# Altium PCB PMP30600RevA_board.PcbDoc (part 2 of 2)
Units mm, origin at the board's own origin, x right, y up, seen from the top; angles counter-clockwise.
Board outline 78.5 x 61.5 mm, 4 copper layers (Top Layer, 2nd Layer, 3rd Layer, Bottom Layer), stack 2.155 mm thick; 62 components, 27 nets, 174 pads, 413 vias.
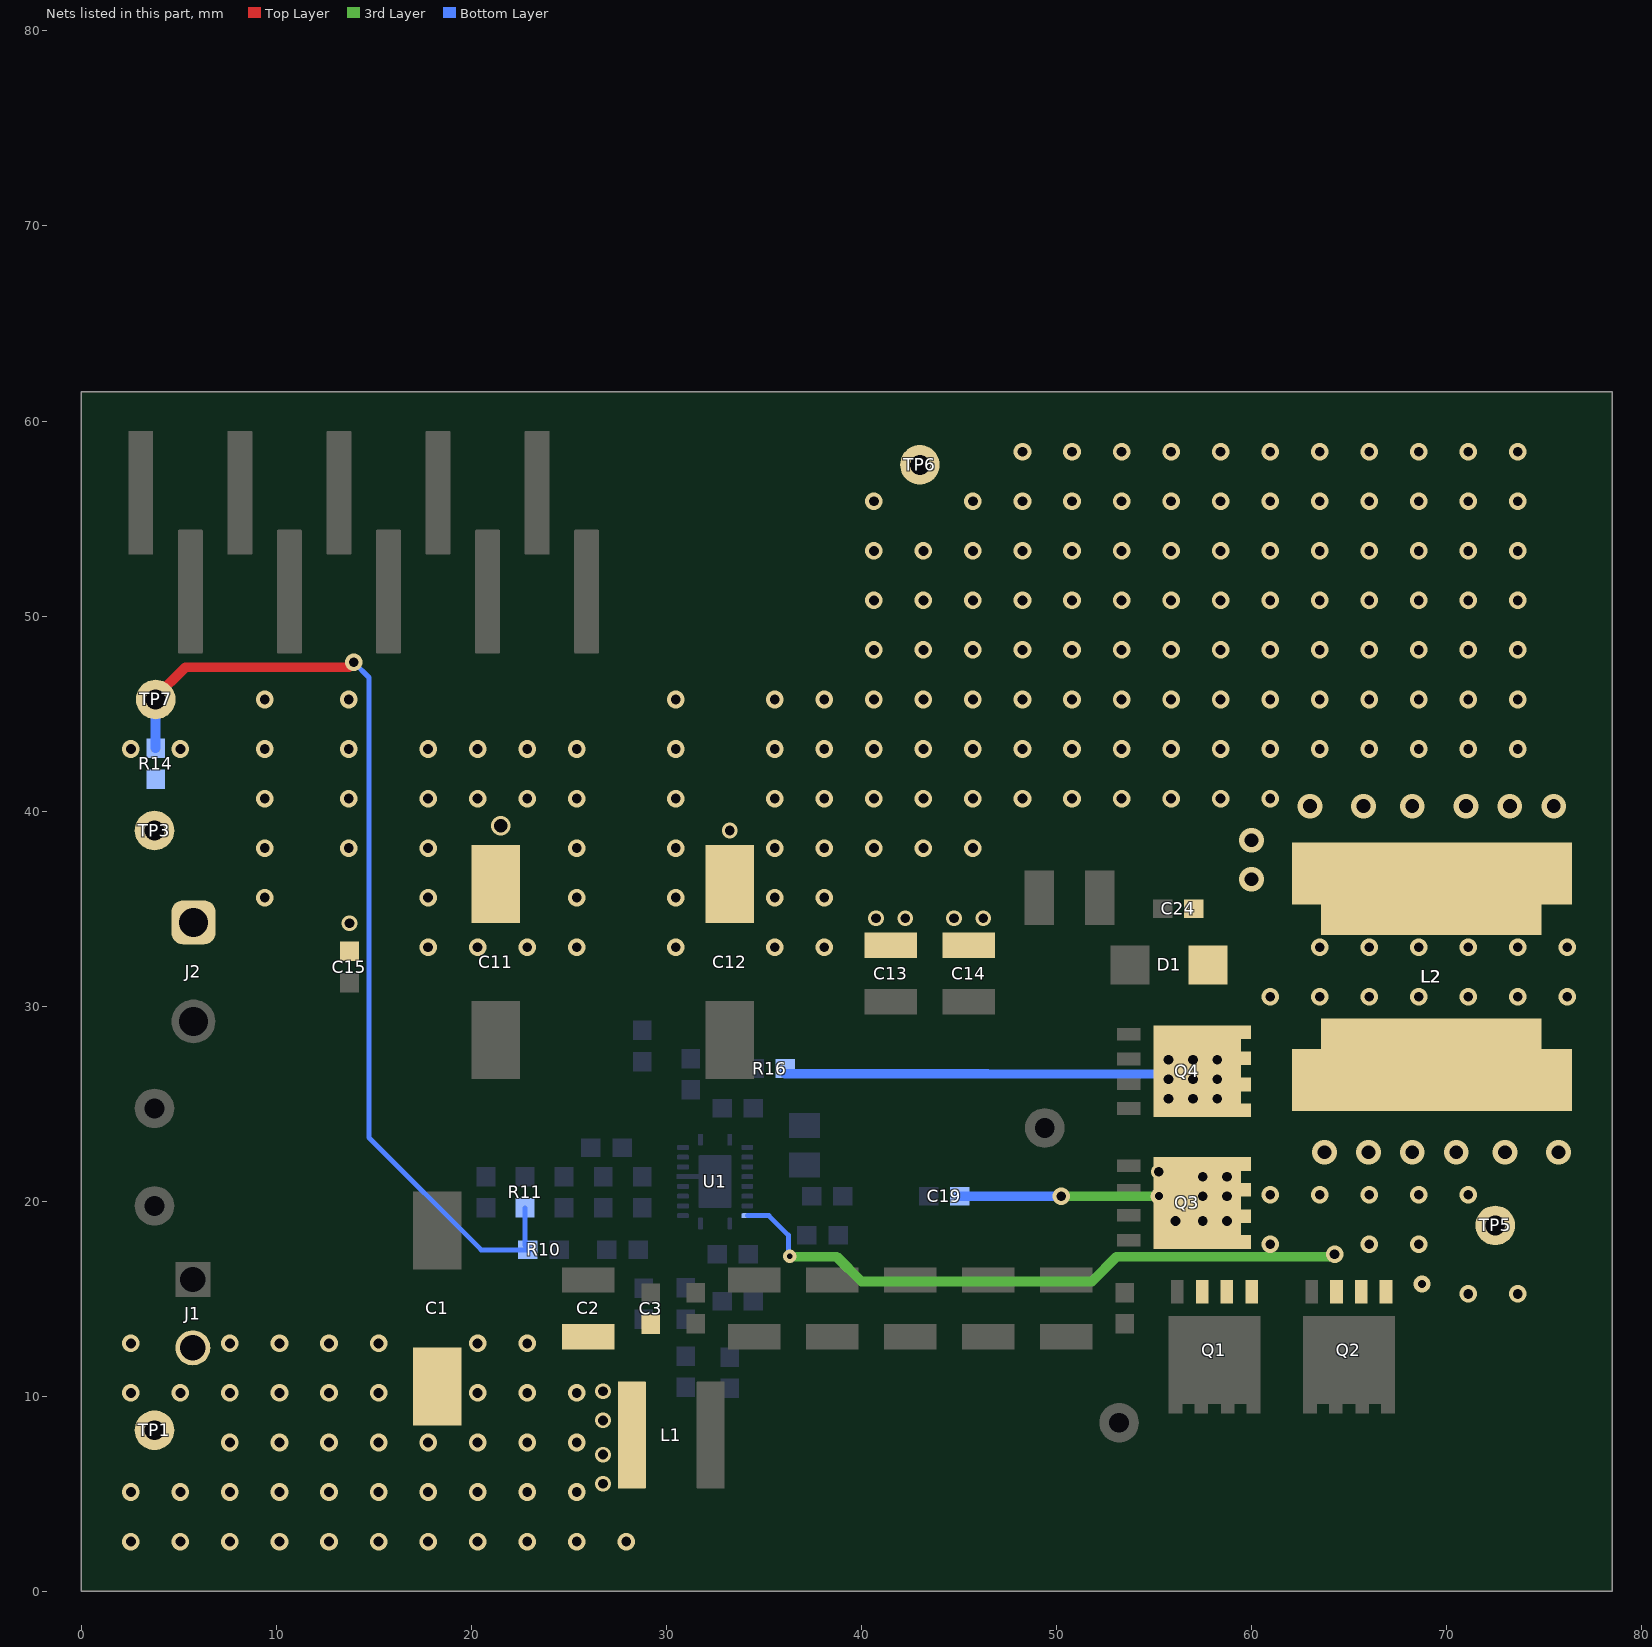
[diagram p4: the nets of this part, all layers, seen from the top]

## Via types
v1: diameter 0.9, hole 0.5, Top Layer to Bottom Layer, 251 vias
v2: diameter 0.9, hole 0.5, Top Layer to Bottom Layer, tented top, 61 vias
v3: diameter 0.8, hole 0.5, Top Layer to Bottom Layer, 57 vias
v4: diameter 0.864, hole 0.406, Top Layer to Bottom Layer, 18 vias
v5: diameter 1.27, hole 0.711, Top Layer to Bottom Layer, 14 vias
v6: diameter 0.6, hole 0.3, Top Layer to Bottom Layer, 4 vias
v7: diameter 0.7, hole 0.3, Top Layer to Bottom Layer, 2 vias
v8: diameter 0.9, hole 0.5, Top Layer to Bottom Layer, tented both sides, 1 vias
v9: diameter 0.7, hole 0.3, Top Layer to Bottom Layer, tented both sides, 1 vias
v10: diameter 0.7, hole 0.3, Top Layer to Bottom Layer, tented bottom, 1 vias
v11: diameter 0.864, hole 0.406, Top Layer to Bottom Layer, tented top, 1 vias
v12: diameter 1, hole 0.7, Top Layer to Bottom Layer, 1 vias
v13: diameter 0.8, hole 0.5, Top Layer to Bottom Layer, tented top, 1 vias

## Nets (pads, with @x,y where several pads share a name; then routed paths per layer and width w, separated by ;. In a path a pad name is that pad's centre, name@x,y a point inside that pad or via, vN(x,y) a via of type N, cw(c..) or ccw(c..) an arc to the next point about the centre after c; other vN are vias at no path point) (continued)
Vo: C11.1 C12.1 C13.1 C14.1 C15.1 J2.1 L2.2 R14.2 TP3.1 TP6.1
  other v1: 9.398,35.56 9.398,38.1 13.716,38.1 40.64,38.1 43.18,38.1 45.72,38.1 9.398,40.64 13.716,40.64 17.78,40.64 20.32,40.64 22.86,40.64 25.4,40.64 30.48,40.64 35.56,40.64 38.1,40.64 40.64,40.64 43.18,40.64 45.72,40.64 48.26,40.64 50.8,40.64 53.34,40.64 55.88,40.64 58.42,40.64 60.96,40.64 2.54,43.18 5.08,43.18 9.398,43.18 13.716,43.18 17.78,43.18 22.86,43.18 25.4,43.18 30.48,43.18 35.56,43.18 38.1,43.18 40.64,43.18 43.18,43.18 45.72,43.18 48.26,43.18 50.8,43.18 53.34,43.18 55.88,43.18 58.42,43.18 60.96,43.18 63.5,43.18 66.04,43.18 68.58,43.18 71.12,43.18 73.66,43.18 9.398,45.72 13.716,45.72 30.48,45.72 35.56,45.72 38.1,45.72 40.64,45.72 43.18,45.72 45.72,45.72 48.26,45.72 50.8,45.72 53.34,45.72 55.88,45.72 58.42,45.72 60.96,45.72 63.5,45.72 66.04,45.72 68.58,45.72 71.12,45.72 73.66,45.72 40.64,48.26 43.18,48.26 45.72,48.26 48.26,48.26 50.8,48.26 53.34,48.26 55.88,48.26 58.42,48.26 60.96,48.26 63.5,48.26 66.04,48.26 68.58,48.26 71.12,48.26 73.66,48.26 40.64,50.8 43.18,50.8 45.72,50.8 48.26,50.8 50.8,50.8 53.34,50.8 55.88,50.8 58.42,50.8 60.96,50.8 63.5,50.8 66.04,50.8 68.58,50.8 71.12,50.8 73.66,50.8 40.64,53.34 43.18,53.34 45.72,53.34 48.26,53.34 50.8,53.34 53.34,53.34 55.88,53.34 58.42,53.34 60.96,53.34 63.5,53.34 66.04,53.34 68.58,53.34 71.12,53.34 73.66,53.34 40.64,55.88 45.72,55.88 48.26,55.88 50.8,55.88 53.34,55.88 55.88,55.88 58.42,55.88 60.96,55.88 63.5,55.88 66.04,55.88 68.58,55.88 71.12,55.88 73.66,55.88 48.26,58.42 50.8,58.42 53.34,58.42 55.88,58.42 58.42,58.42 60.96,58.42 63.5,58.42 66.04,58.42 68.58,58.42 71.12,58.42 73.66,58.42
  other v2: 17.78,33.02 20.32,33.02 22.86,33.02 25.4,33.02 30.48,33.02 35.56,33.02 38.1,33.02 63.5,33.02 66.04,33.02 68.58,33.02 71.12,33.02 73.66,33.02 76.2,33.02 17.78,35.56 25.4,35.56 30.48,35.56 35.56,35.56 38.1,35.56 17.78,38.1 25.4,38.1 30.48,38.1 35.56,38.1 38.1,38.1 20.32,43.18
  other v3: 13.75,34.25 40.75,34.5 42.25,34.5 44.75,34.5 46.25,34.5 33.25,39
  other v5: 60,36.5 60,38.5 63,40.25 65.75,40.25 68.25,40.25 71,40.25 73.25,40.25 75.5,40.25
  other v12: 21.5,39.25
Vod: R10.2 R11.2 R14.1 TP7.1 | length 51
  Top Layer w0.508: TP7.1@3.81,45.847 5.334,47.371 13.716,47.371 v2(13.97,47.625)
  Bottom Layer w0.254: v2(13.97,47.625) 14.75,46.845 14.75,23.25 20.5,17.5 R10.2@22.9,17.5 ; R11.2@22.75,19.65 22.75,17.75 R10.2@23,17.5
  Bottom Layer w0.508: R14.1@3.81,43.218 TP7.1@3.81,45.847
Vsupply: C1.1 C2.1 C3.1 J1.2 L1.2 TP1.1
  other v1: 2.54,2.54 5.08,2.54 7.62,2.54 10.16,2.54 12.7,2.54 15.24,2.54 17.78,2.54 20.32,2.54 22.86,2.54 25.4,2.54 27.94,2.54 2.54,5.08 5.08,5.08 7.62,5.08 10.16,5.08 12.7,5.08 15.24,5.08 17.78,5.08 20.32,5.08 22.86,5.08 25.4,5.08 7.62,7.62 10.16,7.62 12.7,7.62 17.78,7.62 20.32,7.62 22.86,7.62 2.54,10.16 5.08,10.16 7.62,10.16 10.16,10.16 12.7,10.16 25.4,10.16 10.16,12.7 12.7,12.7
  other v2: 15.24,7.62 25.4,7.62 15.24,10.16 20.32,10.16 22.86,10.16 2.54,12.7 7.62,12.7 15.24,12.7 20.32,12.7 22.86,12.7
  other v3: 26.75,5.5 26.75,7 26.75,8.75 26.75,10.25
Vsw: C19.1 C24.1 D1.1 L2.1 Q1.1 Q1.2 Q1.3 Q2.1 Q2.2 Q2.3 Q3.5 Q3.6 Q3.7 Q3.8 Q3.9 Q4.5 Q4.6 Q4.7 Q4.8 Q4.9 R16.1 TP5.1 U1.19 | length 65.3
  Top Layer w0.254: Q4.9@57.218,25.218 Q4.9@57.218,26.652
  3rd Layer w0.5: v1(50.25,20.25) v4(55.25,20.25)
  3rd Layer w0.508: v7@36.322,17.145 38.735,17.145 40.005,15.875 51.816,15.875 53.086,17.145 64.135,17.145 v1(64.262,17.272)
  Bottom Layer w0.254: U1.19@34.15,19.25 35.25,19.25 36.25,18.25 36.25,17.217 v7@36.322,17.145
  Bottom Layer w0.5: R16.1@36.068,26.543 v3@57,26.5 ; C19.1@45.05,20.25 v1(50.25,20.25)
  other v1: 71.12,15.24 73.66,15.24 60.96,17.78 66.04,17.78 68.58,17.78 60.96,20.32 63.5,20.32 66.04,20.32 68.58,20.32 71.12,20.32
  other v2: 60.96,30.48 63.5,30.48 66.04,30.48 68.58,30.48 71.12,30.48 73.66,30.48 76.2,30.48
  other v3: 56.103,18.98 57.5,18.98 58.75,18.98 57.5,20.25 58.75,20.25 57.5,21.25 58.75,21.25 55.25,21.5 55.75,25.25 57,25.25 58.25,25.25 55.75,26.25 57,26.25 58.25,26.25 55.75,27.25 57,27.25 58.25,27.25
  other v4: 68.75,15.75
  other v5: 63.75,22.5 66,22.5 68.25,22.5 70.5,22.5 73,22.5 75.75,22.5
  other v7: 36.322,17.17
pads on no net: U1.9 U1.16 U1.21@32.025,20.295 U1.21@32.025,21.705 U1.21@32.975,20.295 U1.21@32.975,21.705

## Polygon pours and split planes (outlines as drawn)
AGND on Bottom Layer "BOTTOM_LAYER_AGND_P002" (solid, remove dead copper, pour order 2): 31.496,11.557 29.21,11.557 26.924,13.843 26.924,14.732 31.369,14.732 31.496,14.605
GND on Bottom Layer "BOTTOM_LAYER_GND_P004" (solid, remove dead copper, pour order 4): 0.5,31.75 0.5,14.5 52.5,14.5 52.5,31.75
Vsw on Bottom Layer "BOTTOM_LAYER_VSW_P028" (solid, remove dead copper, pour order 28): 56.5,35.75 56.5,30.631 cw(c55.897,30.63) 56.323,30.204 55.604,29.484 cw(c54.427,32.325) 53.25,29.484 53.25,18.5 ccw(c56.621,20.277) 55.494,16.637 57.25,14.881 76.75,14.881 ccw(c76.75,15.881) 77.75,15.881 77.75,30.381 ccw(c77,30.381) 77,31.131 61.54,31.131 cw(c61.54,33.671) 59,33.671 59,34.631 ccw(c57.25,34.631) 56.89,36.343
Vin on Bottom Layer "BOTTOM_LAYER_VIN_P020" (solid, remove dead copper, pour order 20): 30.75,0.75 77.75,0.75 77.75,14.224 30.75,14.224
Vo on Bottom Layer "BOTTOM_LAYER_VO_P021" (solid, remove dead copper, pour order 21): 77.75,32.25 77.75,59.25 38,59.25 38,46.75 0.75,46.75 0.75,32.25
Vsupply on Bottom Layer "BOTTOM_LAYER_VSUPPLY_P019" (solid, remove dead copper, pour order 19): 0.75,14 0.75,0.75 30.25,0.75 30.25,13.75
AGND on 3rd Layer "3RD_LAYER_AGND_P003" (solid, remove dead copper, pour order 3): 30.353,11.684 26.797,11.684 26.797,23.241 30.353,23.241
GND on 3rd Layer "3RD_LAYER_GND_P006" (solid, remove dead copper, pour order 6): 0.5,31.75 54.25,31.75 54.25,14.75 0.5,14.75
Vsw on 3rd Layer "3RD_LAYER_VSW_P027" (solid, remove dead copper, pour order 27): 56.5,35.75 56.5,30.631 cw(c55.897,30.63) 56.323,30.204 55.604,29.484 cw(c54.75,30.338) 54.75,29.131 54.75,18.433 ccw(c57.29,18.433) 55.494,16.637 57.25,14.881 76.75,14.881 ccw(c76.75,15.881) 77.75,15.881 77.75,30.381 ccw(c77,30.381) 77,31.131 61.54,31.131 cw(c61.54,33.671) 59,33.671 59,34.631 ccw(c57.25,34.631) 56.89,36.343
Vin on 3rd Layer "3RD_LAYER_VIN_P017" (solid, remove dead copper, pour order 17): 30.75,14.25 30.75,0.5 78,0.5 78,14.25
Vo on 3rd Layer "3RD_LAYER_VO_P018" (solid, remove dead copper, pour order 18): 77.75,32.75 77.75,59.5 38,59.5 38,46.75 0.5,46.75 0.5,32.75
Vsupply on 3rd Layer "3RD_LAYER_VSUPPLY_P016" (solid, remove dead copper, pour order 16): 0.75,14 0.75,0.5 30.25,0.5 30.25,13.75 30,14
GND on Top Layer "TOP_LAYER_GND_P005" (solid, remove dead copper, pour order 5): 52.959,33.528 51.054,33.528 50.165,34.417 50.165,36.957 48.26,36.957 47.879,36.576 47.879,32.131 47.117,31.369 47.498,30.988 52.959,30.988
no net on Top Layer "TOP_LAYER_NONET_P030" (solid, remove dead copper, pour order 30): 52.959,37.465
NetC24_2 on Top Layer "TOP_LAYER_NETC24_2_P029" (solid, remove dead copper, pour order 29): 51.435,37.084 51.435,34.036 55.626,34.036 55.88,34.29 55.88,35.941 54.737,37.084
Vsw on Top Layer "TOP_LAYER_VSW_P025" (solid, remove dead copper, pour order 25): 56.5,35.5 56.5,30.381 cw(c55.897,30.38) 56.323,29.954 55.604,29.234 cw(c54.75,30.087) 54.75,28.881 54.75,18.183 ccw(c57.29,18.183) 55.494,16.387 57.25,14.631 76.75,14.631 ccw(c76.75,15.631) 77.75,15.631 77.75,30.131 ccw(c77,30.131) 77,30.881 62.395,31.253 cw(c62.217,34.009) 59.461,33.832 ccw(c56.776,33.371) 56.89,36.093
GND on Top Layer "TOP_LAYER_GND_P008" (solid, remove dead copper, pour order 8): 0.5,31.75 52,31.75 52,33.5 55.25,33.5 55.25,30.25 54.25,30.25 54.25,14.75 0.5,14.75
Vsw on Top Layer "TOP_LAYER_VSW_P024" (solid, remove dead copper, pour order 24): 56.5,35.619 56.5,30.5 cw(c55.897,30.5) 56.323,30.073 55.604,29.354 cw(c54.75,30.207) 54.75,29 54.75,18.302 ccw(c57.29,18.302) 55.494,16.506 57.25,14.75 76.75,14.75 ccw(c76.75,15.75) 77.75,15.75 77.75,30.25 ccw(c77,30.25) 77,31 61.54,31 cw(c61.54,33.54) 59,33.54 59,34.5 ccw(c57.25,34.5) 56.89,36.212
Vin on Top Layer "TOP_LAYER_VIN_P014" (solid, remove dead copper, pour order 14): 30.75,14.25 78.25,14.25 78.25,0.25 30.75,0.25
Vo on Top Layer "TOP_LAYER_VO_P015" (solid, remove dead copper, pour order 15): 78,32.75 62,32.75 58,36.75 47.799,36.75 47.5,36.451 47.5,32.25 0.5,32.25 0.5,46.75 37.75,46.75 37.75,59.75 78,59.75
Vsupply on Top Layer "TOP_LAYER_VSUPPLY_P013" (solid, remove dead copper, pour order 13): 0.5,14.25 0.5,0.5 30.25,0.5 30.25,14.25
GND on Top Layer "TOP_LAYER_GND_P007" (solid, remove dead copper, pour order 7): 0.5,31.75
GND on 2nd Layer "2ND_LAYER_GND_P009" (solid, remove dead copper, pour order 9): 0.5,31.75 54.25,31.75 54.25,14.75 0.5,14.75
Vsw on 2nd Layer "2ND_LAYER_VSW_P026" (solid, remove dead copper, pour order 26): 56.5,35.619 56.5,30.5 cw(c55.897,30.5) 56.323,30.073 55.604,29.354 cw(c54.75,30.207) 54.75,29 54.75,18.302 ccw(c57.29,18.302) 55.494,16.506 57.25,14.75 76.75,14.75 ccw(c76.75,15.75) 77.75,15.75 77.75,30.25 ccw(c77,30.25) 77,31 61.54,31 cw(c61.54,33.54) 59,33.54 59,34.5 ccw(c57.25,34.5) 56.89,36.212
Vin on 2nd Layer "2ND_LAYER_VIN_P012" (solid, remove dead copper, pour order 12): 30.75,14.25 78,14.25 78,0.25 30.75,0.25
Vo on 2nd Layer "2ND_LAYER_VO_P022" (solid, remove dead copper, pour order 22): 38,46.75 38,59.5 77.75,59.5 77.75,46.75
Vsupply on 2nd Layer "2ND_LAYER_VSUPPLY_P011" (solid, remove dead copper, pour order 11): 0.5,14 30.25,14 30.25,0.5 0.5,0.5
Vo on 2nd Layer "2ND_LAYER_VO_P010" (solid, remove dead copper, pour order 10): 0.5,46.75 78,46.75 78,32.25 77.5,32.75 0.5,32.75

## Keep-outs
Top Layer:
  region: 0.75,23
Keep-Out Layer:
  text ".Layer_Name" at 14.656,-21.806 h1.52

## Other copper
Top Layer:
  pour cut-out: 13.25,22.75 13.25,21.5 0.5,21.5 0.5,22.75
  region: 51.308,8.606
  pour cut-out: 27.623,78.67
2nd Layer:
  pour cut-out: 13.25,22.75 13.25,21.5 0.5,21.5 0.5,22.75
  region: 78,14.25
3rd Layer:
  pour cut-out: 13.25,22.75 13.25,21.5 0.5,21.5 0.5,22.75
  region: 53.5,14.75
Bottom Layer:
  pour cut-out: 32.055,19.304 32.055,19.634 31.496,19.634 31.496,19.304
  pour cut-out: 31.648,22.936 31.648,22.301 32.106,22.301 32.106,22.911
  pour cut-out: 33.452,22.86 33.452,22.301 32.944,22.301 32.944,22.86
  pour cut-out: 33.325,22.835 33.325,19.456 33.884,19.456 33.884,22.835
  pour cut-out: 31.648,19.583 31.648,22.885 31.039,22.885 31.039,19.583
  pour cut-out: 32.969,19.66 32.969,19.101 33.858,19.101 33.858,19.66
  pour cut-out: 0.5,22.75 0.5,21.5 8.25,21.5 8.25,22.75

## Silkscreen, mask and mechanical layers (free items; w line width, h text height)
Top Overlay:
  text "GND" at 1.778,60.071 h1
  text "GND" at 6.604,60.071 h1
  text "SS" at 12.7,60.071 h1
  text "TRIM" at 17.145,60.071 h1
  text "SYNCIN" at 22.352,60.071 h1
  text "Vo" at 46,56.75 h1.85 r90
  text "PMP30600A" at 58.42,48.768 h1.5
  text "EN" at 11,46.5 h1 r90
  text "LM5146-Q1" at 58.42,46.482 h0.8
  text "GND" at 6.096,45.974 h1 r90
  text "VCC" at 26.25,45.5 h1 r90
  text "PGOOD" at 16,44.5 h1 r90
  text "SYNCOUT" at 21.25,43.25 h1 r90
  text "Vod" at 6.985,42.418 h1.85 r90
  text "Vo" at 6.75,38.25 h1.85 r90
  text "VgL" at 46.863,25.908 h1.85
  text "GND" at 6.75,20.5 h1.85 r90
  text "Vsw" at 75.5,17.25 h1.85 r90
  text "Vin" at 6.75,7.25 h1.85 r90
  text "VgH" at 51.562,3.429 h1.85
  text "12/2018" at 72.238,1.168 h0.8
Bottom Overlay:
  text ".Layer_Name" at 14.656,-21.806 h1.52
Bottom Paste:
  text ".Layer_Name" at 14.656,-21.806 h1.52
Bottom Solder:
  text ".Layer_Name" at 14.656,-21.806 h1.52
Drill Guide:
  text ".Layer_Name" at 14.656,-21.806 h1.52
M1 Board Outline:
  the board outline again, w0.3
  text ".Layer_Name" at 14.656,-21.806 h1.52
M2 Board Dimensions:
  lines w0.178: 0,-10.16 25.4,-10.16
  text "'.Print_Date' '.Print_Time'" at 0.102,63.881 h1.85
  text ".Layer_Name" at 14.656,-21.806 h1.52
M3 3D STEP Top:
  text ".Layer_Name" at 14.656,-21.806 h1.52
M4 3D STEP Bottom:
  text ".Layer_Name" at 14.656,-21.806 h1.52
M5 Assembly Top:
  lines w0.254: -7.417,-23.626 160.223,-23.626 ; -7.417,-18.462 160.274,-18.462 ; -7.417,-13.297 -7.417,-28.791 94.31,-28.791 160.274,-28.791 160.274,-13.297 -7.404,-13.297 -7.404,-28.791 32.614,-28.791 ; 55.194,-28.791 55.194,-13.297 ; 87.376,-18.462 87.376,-13.297 ; 108.712,-18.462 108.712,-13.297 ; 124.511,-28.956 124.511,-23.804
  text "ASSEMBLY VARIANT:" at 29.286,-11.024 h1.52
  text ".VariantName" at 55.601,-11.024 h1.52
  text "PCB VIEWED FROM TOP SIDE" at -5.804,-16.654 h1.52
  text "BOARD #:" at 57.099,-16.654 h1.52
  text ".PRJ_Number" at 70.955,-16.654 h1.52
  text "REV:" at 92.405,-16.654 h1.52
  text ".PCB_Rev" at 99.809,-16.654 h1.52
  text "SVN REV:" at 113.69,-16.654 h1.52
  text ".VersionControl_RevNumber" at 126.543,-16.654 h1.52
  text "TID #:" at 57.099,-21.819 h1.52
  text ".TID" at 70.955,-21.819 h1.52
  text "PLOT NAME =" at -5.804,-27.034 h1.52
  text ".plot_File_Name" at 14.656,-27.034 h1.52
  text "GENERATED    :" at 57.15,-27.034 h1.52
  text ".Print_Date" at 79.235,-27.034 h1.52
  text ".Print_Time" at 97.752,-27.034 h1.52
  text "TEXAS INSTRUMENTS" at 129.87,-27.034 h1.52
M6 Assembly Bottom:
  lines w0.254: -7.429,-18.474 160.261,-18.474 ; -7.379,-23.639 160.261,-23.639 ; 28.334,-28.969 28.334,-23.817 ; 44.133,-18.474 44.133,-13.31 ; 65.468,-18.474 65.468,-13.31 ; 97.65,-28.804 97.65,-13.31 ; 120.231,-28.804 160.249,-28.804 160.249,-13.31 -7.429,-13.31 -7.429,-28.804 58.534,-28.804 160.261,-28.804 160.261,-13.31
  text ".VariantName" at 128.473,-11.024 h1.52
  text "ASSEMBLY VARIANT:" at 154.864,-11.024 h1.52
  text ".VersionControl_RevNumber" at 26.302,-16.667 h1.52
  text "SVN REV:" at 39.154,-16.667 h1.52
  text ".PCB_Rev" at 53.035,-16.667 h1.52
  text "REV:" at 60.439,-16.667 h1.52
  text ".PRJ_Number" at 81.89,-16.667 h1.52
  text "BOARD #:" at 95.745,-16.667 h1.52
  text "PCB VIEWED FROM BOTTOM SIDE" at 158.648,-16.667 h1.52
  text ".TID" at 81.89,-21.831 h1.52
  text "TID #:" at 95.745,-21.831 h1.52
  text "TEXAS INSTRUMENTS" at 22.974,-27.047 h1.52
  text ".Print_Time" at 55.093,-27.047 h1.52
  text ".Print_Date" at 73.609,-27.047 h1.52
  text "GENERATED    :" at 95.694,-27.047 h1.52
  text ".plot_File_Name" at 138.189,-27.047 h1.52
  text "PLOT NAME =" at 158.648,-27.047 h1.52
M9 Title Sheet:
  drawing of 54 lines, arcs and shapes, not listed
  text "1" at 18.792,204.127 h1.78
  text "2" at 82.182,204.127 h1.78
  text "3" at 145.411,204.127 h1.78
  text "4" at 209.08,204.127 h1.78
  text "5" at 272.555,204.127 h1.78
  text "6" at 336.182,204.127 h1.78
  text "A" at -10.579,175.095 h1.78
  text "A" at 365.341,175.095 h1.78
  text "PROJECT TITLE:" at 133.603,166.003 h1.14
  text ".PRJ_Title" at 133.353,162.753 h1.78
  text "B" at 350.507,119.713 h1.78
  text "B" at -14.738,116.393 h1.78
  text "C" at -10.579,54.318 h1.78
  text "C" at 365.341,54.318 h1.78
  text "DESIGNED FOR:" at 288.125,-0.597 h1.14
  text ".PRJ_Customer" at 289.395,-4.153 h1.78
  text "D" at -10.579,-5.88 h1.78
  text "D" at 365.341,-5.88 h1.78
  text "FILE NAME:" at 288.125,-8.217 h1.14
  text ".PCB_File_Name_No_Path" at 289.395,-11.265 h1.78
  text "Texas Instruments (TI) and/or its licensors do not warrant the accuracy or completeness of this specification" at 161.9,-15.376 h1.14
  text "ENGINEER:" at 288.125,-15.583 h1.14
  text "LAYOUT BY:" at 326.352,-15.583 h1.14
  text "or any information contained therein. TI and/or its licensors do not warrant that this design will meet" at 160.757,-18.237 h1.14
  text ".PRJ_Engineer" at 289.395,-19.52 h1.78
  text ".PCB_Layout" at 327.635,-19.52 h1.78
  text "the specifications, will be suitable for your application or fit for any particular purpose, or will operate in" at 160.757,-21.099 h1.14
  text ".Layer_Name" at 14.656,-21.806 h1.52
  text "ALTIUM DESIGNER VERSION:" at 326.352,-23.457 h1.14
  text "an implementation. TI and/or its licensors do not warrant that the design is production worthy. You should" at 160.757,-23.961 h1.14
  text "completely validate and test your design implementation to confirm the system functionality for your application." at 161.9,-26.822 h1.14
  text ".print_Scale" at 289.395,-26.843 h1.78
  text ".Application_BuildNumber" at 327.635,-26.843 h1.78
  text "1" at 18.792,-32.093 h1.78
  text "2" at 82.182,-32.093 h1.78
  text "3" at 145.411,-32.093 h1.78
  text "4" at 209.08,-32.093 h1.78
  text "5" at 272.555,-32.093 h1.78
  text "6" at 336.182,-32.093 h1.78
M10 Fab Notes:
  drawing of 183 lines, arcs and shapes, not listed
  text "LAYER 2 & 3 (INNER LAYERS) XX MIL WIDE, XX MIL SPACE / TRACES REQUIRE 100 OHM DIFFERENTIAL IMPEDANCE" at 134.246,171.252 h1.52
  text "DESIGN INFORMATION" at 314.503,161.447 h1.52
  text "MIN. TRACK WIDTH:" at 298.131,158.091 h1.52
  text "8" at 325.976,158.091 h1.52
  text "MIL" at 329.907,158.091 h1.52
  text "MIN. CLEARANCE:" at 298.131,154.938 h1.52
  text "0.2" at 324.452,154.938 h1.52
  text "mm" at 329.907,154.938 h1.52
  text "MIN. VIA PAD SIZE:" at 298.131,151.785 h1.52
  text "24" at 325.214,151.785 h1.52
  text "MIL" at 329.907,151.785 h1.52
  text "DRILLING:" at 170.75,149 h1.52
  text "0.05mm (2MIL)" at 315.784,148.486 h1.52
  text "MINIMUM ANNULAR RING" at 289.769,148.277 h1.52
  text "EXTERNAL" at 333.768,148.277 h1.52
  text "PER" at 294.849,145.48 h1.52
  text "IPC-D-275 CLASS 2 LEVEL C" at 300.437,145.48 h1.52
  text "MIL, HOLES" at 338.238,142.928 h1.52
  text "+/-" at 328.27,142.709 h1.52
  text "+/-" at 349.961,142.709 h1.52
  text "REGISTRATION TOLERANCES:" at 289.769,142.682 h1.52
  text "METAL" at 320.243,142.682 h1.52
  text "5" at 334.879,142.683 h1.52
  text "3" at 356.037,142.683 h1.52
  text "MIL" at 358.99,142.682 h1.52
  text "HOLE SIZE TOLERANCE (UNLESS OTHERWISE SPECIFIED):" at 289.769,140.185 h1.52
  text "+/-" at 349.961,140.112 h1.52
  text "3" at 356.037,140.085 h1.52
  text "MIL" at 358.99,140.085 h1.52
  text "MATERIAL:" at 287.87,136.589 h1.52
  text "FR-4 High Tg" at 312.926,133.324 h1.52
  text "X" at 309.257,133.122 h1.52
  text "FR-408" at 298.563,133.007 h1.52
  text "OTHER" at 336.358,133.007 h1.52
  text "62 MIL (1.6mm) +/-10%" at 306.694,129.374 h1.52
  text "X" at 303.643,129.312 h1.52
  text "THICKNESS:" at 289.769,129.165 h1.52
  text "OTHER" at 339.33,129.165 h1.52
  text "TOLERANCE:" at 289.769,125.652 h1.52
  text "X" at 311.314,125.652 h1.52
  text "ANSI IPC-6012 TYPE 3 CLASS 2" at 315.836,125.652 h1.52
  text "OTHER +/-" at 315.835,121.989 h1.52
  text "OTHER +/-" at 301.001,119.646 h1.52
  text "BOW & TWIST:" at 289.769,118.302 h1.52
  text "X" at 311.314,118.302 h1.52
  text "NC_DRILL FILES" at 317.765,113.656 h1.52
  text "ANSI IPC-6012 TYPE 3 CLASS 2" at 242.727,113.622 h1.52
  text "REFERENCE:" at 274.935,113.556 h1.52
  text "X" at 291.628,113.554 h1.52
  text "AS SHOWN" at 296.15,113.556 h1.52
  text "X" at 314.514,113.556 h1.52
  text "OTHER" at 325.334,109.943 h1.52
  text "PTH COPPER THICKNESS:" at 274.926,109.853 h1.52
  text "X" at 303.863,109.853 h1.52
  text "20-30 um" at 307.114,109.853 h1.52
  text "BOARD FINISH:" at 273.036,106.104 h1.52
  text "SILKSCREEN:" at 276.978,103.307 h1.52
  text "X" at 301.306,103.307 h1.52
  text "TOP" at 304.278,103.307 h1.52
  text "X" at 314.26,103.307 h1.52
  text "BOTTOM" at 317.257,103.307 h1.52
  text "SILKSCREEN COLOR:" at 276.978,99.365 h1.52
  text "X" at 301.28,99.365 h1.52
  text "WHITE" at 304.278,99.365 h1.52
  text "OTHER" at 317.257,99.365 h1.52
  text "X" at 304.608,95.722 h1.52
  text "GREEN" at 307.605,95.722 h1.52
  text "OTHER" at 323.302,95.722 h1.52
  text "SOLDER RESIST COLOR:" at 276.978,95.547 h1.52
  text "X" at 319.442,86.734 h1.52
  text "MATTE" at 322.439,86.734 h1.52
  text "SEMI-GLOSS" at 338.125,86.717 h1.52
  text "IMMERSION GOLD (ENIG)" at 314.819,82.345 h1.52
  text "ENEPIG" at 348.793,82.162 h1.52
  text "SURFACE FINISH:" at 287.87,82.136 h1.52
  text "X" at 310.298,82.136 h1.52
  text "IMM. TIN/SILVER OR EQUIV" at 296.24,78.649 h1.52
  text "OTHER" at 332.599,78.549 h1.52
  text "ARRAY/PANEL:" at 287.87,74.602 h1.52
  text "CUT AND TRIM PER M1 BOARD OUTLINE" at 314.819,74.393 h1.52
  text "N.C. ROUTE" at 314.819,70.94 h1.52
  text "X" at 332.295,70.94 h1.52
  text "V. SCORE" at 336.816,70.94 h1.52
  text "CERTIFICATION:" at 287.87,67.66 h1.52
  text "MATERIALS AND WORKMANSHIP FOR ALL PCBS" at 306.285,67.66 h1.52
  text "TO MEET OR EXCEED THE REQUIREMENTS OF:" at 306.285,65.271 h1.52
  text "X" at 297.078,62.003 h1.52
  text "ANSI IPC-A-600F CLASS ->" at 300.329,62.003 h1.52
  text "X" at 342.188,62.003 h1.52
  text "2" at 344.982,62.003 h1.52
  text "1" at 336.981,61.965 h1.52
  text "3" at 353.973,61.965 h1.52
  text "X" at 317.702,58.252 h1.52
  text "RoHS" at 320.953,58.252 h1.52
  text "OTHER" at 337.321,58.252 h1.52
  text "PER ORDER" at 347.407,58.252 h1.52
  text "ALL BOARDS MUST MEET OR EXCEED UL94-V0 REQUIREMENTS." at 288.569,54.345 h1.52
  text "PCB MUST BEAR THE UL94V-0 UL REGISTERED MATERIAL ID NUMBER" at 288.569,51.397 h1.52
  text "ADDITIONAL REQUIREMENTS:" at 287.87,47.094 h1.52
  text "MICROSECTION:" at 289.769,44.373 h1.52
  text "YES" at 312.775,44.373 h1.52
  text "REQUIRED" at 334.657,40.707 h1.52
  text "BARE BOARD ELEC. TEST:" at 289.769,40.634 h1.52
  text "NONE" at 322.935,40.634 h1.52
  text "X" at 331.66,40.634 h1.52
  text "PER ORDER" at 349.693,40.634 h1.52
  text "XX MIL VIAS REQUIRE NON-CONDUCTIVE FILL AND PLANARIZE" at 294.04,35.428 h1.5
  text "XX MIL VIAS REQUIRE CONDUCTIVE FILL AND PLANARIZE" at 294.243,32.787 h1.52
  text "OUTER XX MIL TRACES REQUIRE 50 OHM SINGLE-ENDED IMPEDANCE" at 294.218,28.637 h1.47
  text ".Layer_Name" at 14.656,-21.806 h1.52
M11 Gerber Information:
  lines w0.254: -7.417,-23.626 160.223,-23.626 ; -7.417,-18.462 160.274,-18.462 ; -7.417,-13.297 -7.417,-28.791 94.31,-28.791 160.274,-28.791 160.274,-13.297 -7.404,-13.297 -7.404,-28.791 32.614,-28.791 ; 55.194,-28.791 55.194,-13.297 ; 87.376,-18.462 87.376,-13.297 ; 108.712,-18.462 108.712,-13.297 ; 124.511,-28.956 124.511,-23.804
  text "ALL ARTWORK VIEWED FROM TOP SIDE" at -5.804,-16.654 h1.52
  text "BOARD #:" at 57.099,-16.654 h1.52
  text ".PRJ_Number" at 70.955,-16.654 h1.52
  text "REV:" at 92.405,-16.654 h1.52
  text ".PCB_Rev" at 99.809,-16.654 h1.52
  text "SVN REV:" at 113.69,-16.654 h1.52
  text ".VersionControl_RevNumber" at 126.543,-16.654 h1.52
  text "LAYER NAME =" at -5.804,-21.806 h1.52
  text "TID #:" at 57.099,-21.819 h1.52
  text ".TID" at 70.955,-21.819 h1.52
  text "PLOT NAME =" at -5.804,-27.034 h1.52
  text ".plot_File_Name" at 14.656,-27.034 h1.52
  text "GENERATED    :" at 57.15,-27.034 h1.52
  text ".Print_Date" at 79.235,-27.034 h1.52
  text ".Print_Time" at 97.752,-27.034 h1.52
  text "TEXAS INSTRUMENTS" at 129.87,-27.034 h1.52
M12 Stackup:
  drawing of 295 lines, arcs and shapes, not listed
  text "Layer" at 249.215,183.45 h1.52
  text "Name" at 259.626,183.45 h1.52
  text "Material" at 283.242,183.45 h1.52
  text "Thickness" at 305.08,183.45 h1.52
  text "Constant" at 321.586,183.45 h1.52
  text "Board Layer Stack" at 336.06,183.45 h1.52
  text "1" at 249.215,180.402 h1.52
  text "Top Overlay" at 259.626,180.402 h1.52
  text "2" at 249.215,177.354 h1.52
  text "Top Solder" at 259.626,177.354 h1.52
  text "Solder Resist" at 283.242,177.354 h1.52
  text "0.40mil" at 305.08,177.354 h1.52
  text "3.5" at 321.586,177.354 h1.52
  text "3" at 249.215,174.306 h1.52
  text "Top Layer" at 259.626,174.306 h1.52
  text "Copper" at 283.242,174.306 h1.52
  text "1.40mil" at 305.08,174.306 h1.52
  text "4" at 249.215,171.258 h1.52
  text "Dielectric 2" at 259.626,171.258 h1.52
  text "10.00mil" at 305.08,171.258 h1.52
  text "4.2" at 321.586,171.258 h1.52
  text "5" at 249.215,168.21 h1.52
  text "2nd Layer" at 259.626,168.21 h1.52
  text "Copper" at 283.242,168.21 h1.52
  text "1.42mil" at 305.08,168.21 h1.52
  text "6" at 249.215,165.162 h1.52
  text "Dielectric1" at 259.626,165.162 h1.52
  text "FR-4" at 283.242,165.162 h1.52
  text "59.20mil" at 305.08,165.162 h1.52
  text "4.8" at 321.586,165.162 h1.52
  text "7" at 249.215,162.114 h1.52
  text "3rd Layer" at 259.626,162.114 h1.52
  text "Copper" at 283.242,162.114 h1.52
  text "1.42mil" at 305.08,162.114 h1.52
  text "8" at 249.215,159.066 h1.52
  text "Dielectric 3" at 259.626,159.066 h1.52
  text "10.00mil" at 305.08,159.066 h1.52
  text "4.2" at 321.586,159.066 h1.52
  text "9" at 249.215,156.018 h1.52
  text "Bottom Layer" at 259.626,156.018 h1.52
  text "Copper" at 283.242,156.018 h1.52
  text "1.40mil" at 305.08,156.018 h1.52
  text "10" at 249.215,152.97 h1.52
  text "Bottom Solder" at 259.626,152.97 h1.52
  text "Solder Resist" at 283.242,152.97 h1.52
  text "0.40mil" at 305.08,152.97 h1.52
  text "3.5" at 321.586,152.97 h1.52
  text "11" at 249.215,149.922 h1.52
  text "Bottom Overlay" at 259.626,149.922 h1.52
  text ".Layer_Name" at 14.656,-21.806 h1.52
M13 Component Bodies Top:
  text ".Layer_Name" at 14.656,-21.806 h1.52
M14 Component Bodies Bottom:
  text ".Layer_Name" at 14.656,-21.806 h1.52
M15 Courtyards Top:
  text ".Layer_Name" at 14.656,-21.806 h1.52
M16 Courtyards Bottom:
  text ".Layer_Name" at 14.656,-21.806 h1.52
Drill Drawing:
  circle w0.254: c169.759,9.746 r0.703
  circle w0.254: c169.759,3.421 r0.422
  circle w0.254: c169.759,3.421 r0.703
  lines w0.254: 169.056,-8.525 170.462,-8.525 169.759,-9.93 169.056,-8.525 ; 169.056,-6.417 169.407,-6.417 169.759,-6.768 170.11,-6.417 170.462,-6.417 170.11,-6.065 170.462,-5.714 170.11,-5.714 169.759,-5.363 169.407,-5.714 169.056,-5.714 169.407,-6.065 169.056,-6.417 ; 169.056,-3.606 170.462,-3.606 170.462,-2.2 169.056,-2.2 169.056,-3.606 ; 169.056,-0.092 169.407,-0.092 169.407,-0.444 170.11,-0.444 170.11,-0.092 170.462,-0.092 170.462,0.611 170.11,0.611 170.11,0.962 169.407,0.962 169.407,0.611 169.056,0.611 169.056,-0.092 ; 169.056,6.584 169.759,5.881 170.462,6.584 169.759,7.286 169.056,6.584 ; 169.056,12.206 169.056,12.557 169.407,12.908 169.056,13.26 169.056,13.611 169.407,13.611 169.759,13.26 170.11,13.611 170.462,13.611 170.462,13.26 170.11,12.908 170.462,12.557 170.462,12.206 170.11,12.206 169.759,12.557 169.407,12.206 169.056,12.206
  lines w0.305: 167.782,-10.879 249.88,-10.879 ; 167.782,14.419 249.88,14.419 ; 176.368,-14.041 176.368,17.582 ; 184.804,-14.041 184.804,17.582 ; 200.971,-14.041 200.971,17.582 ; 207.555,-14.041 207.555,17.582 ; 217.086,-14.041 217.086,17.582 ; 235.489,-14.041 235.489,17.582 ; 167.782,-14.041 249.88,-14.041 249.88,17.582 167.782,17.582 167.782,-14.041
  text "Symbol" at 169.679,15.368 h1.83
  text "Quantity" at 177.316,15.368 h1.83
  text "Finished Hole Size" at 185.753,15.368 h1.83
  text "Plated" at 201.92,15.368 h1.83
  text "Hole Type" at 208.503,15.368 h1.83
  text "Drill Layer Pair" at 218.034,15.368 h1.83
  text "Hole Tolerance" at 236.438,15.368 h1.83
  text "8" at 177.316,12.206 h1.52
  text "11.81mil (0.300mm)" at 185.753,12.206 h1.52
  text "PTH" at 201.92,12.206 h1.52
  text "Round" at 208.503,12.206 h1.52
  text "Top Layer - Bottom Layer" at 218.034,12.206 h1.52
  text "19" at 177.316,9.043 h1.52
  text "16.00mil (0.406mm)" at 185.753,9.043 h1.52
  text "PTH" at 201.92,9.043 h1.52
  text "Round" at 208.503,9.043 h1.52
  text "Top Layer - Bottom Layer" at 218.034,9.043 h1.52
  text "371" at 177.316,5.881 h1.52
  text "19.69mil (0.500mm)" at 185.753,5.881 h1.52
  text "PTH" at 201.92,5.881 h1.52
  text "Round" at 208.503,5.881 h1.52
  text "Top Layer - Bottom Layer" at 218.034,5.881 h1.52
  text "1" at 177.316,2.719 h1.52
  text "27.56mil (0.700mm)" at 185.753,2.719 h1.52
  text "PTH" at 201.92,2.719 h1.52
  text "Round" at 208.503,2.719 h1.52
  text "Top Layer - Bottom Layer" at 218.034,2.719 h1.52
  text "14" at 177.316,-0.444 h1.52
  text "28.00mil (0.711mm)" at 185.753,-0.444 h1.52
  text "PTH" at 201.92,-0.444 h1.52
  text "Round" at 208.503,-0.444 h1.52
  text "Top Layer - Bottom Layer" at 218.034,-0.444 h1.52
  text "9" at 177.316,-3.606 h1.52
  text "40.00mil (1.016mm)" at 185.753,-3.606 h1.52
  text "PTH" at 201.92,-3.606 h1.52
  text "Round" at 208.503,-3.606 h1.52
  text "Top Layer - Bottom Layer" at 218.034,-3.606 h1.52
  text "2" at 177.316,-6.768 h1.52
  text "51.18mil (1.300mm)" at 185.753,-6.768 h1.52
  text "PTH" at 201.92,-6.768 h1.52
  text "Round" at 208.503,-6.768 h1.52
  text "Top Layer - Bottom Layer" at 218.034,-6.768 h1.52
  text "2" at 177.316,-9.93 h1.52
  text "59.06mil (1.500mm)" at 185.753,-9.93 h1.52
  text "PTH" at 201.92,-9.93 h1.52
  text "Round" at 208.503,-9.93 h1.52
  text "Top Layer - Bottom Layer" at 218.034,-9.93 h1.52
  text "426 Total" at 177.316,-13.093 h1.52
  text ".Layer_Name" at 14.656,-21.806 h1.52
M17 Embedded Cavity:
  text ".Layer_Name" at 14.656,-21.806 h1.52
M18 Embedded Assembly:
  text ".Layer_Name" at 14.656,-21.806 h1.52
M19 Embedded Keepout:
  text ".Layer_Name" at 14.656,-21.806 h1.52

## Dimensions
0,0 to 0,61.5 on M2 Board Dimensions
0,0 to 78.5,0 on M2 Board Dimensions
